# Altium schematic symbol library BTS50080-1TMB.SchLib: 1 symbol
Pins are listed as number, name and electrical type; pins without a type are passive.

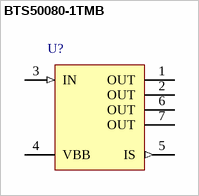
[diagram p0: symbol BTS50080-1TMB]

## BTS50080-1TMB
designator U?
Smart High-Side Power Switch PROFET, 1 Channel, 12 A Load Current, -40 to 150 degC, PG-TO220-7-12, Reel, Green; Manufacturer: Infineon; PartNumber: BTS50080-1TMB; Channels: 1; Green: TRUE; Group: Automotive Qualified; Load Current (typ): 12 A; Ptot (max): 81 W; Recommended Operating Voltage Max.: 38 V; Recommended Operating Voltage Min.: 5.5 V; RON @ 25degreesC: 8 mOhm; RON(max) @ 150degreesC: 16 mOhm; toff (max): 600 us; ton (max): 550 us
footprint INF-PG-TO220-7-12 (FM, 7-Leads, Body 10x4.4mm, Pitch 1.27mm)
pins: 1 OUT (power) "Output to the load. The pins1,2,6 and 7 must be shorted with each other especially in high current applications!", 2 OUT (power) "Output to the load. The pins1,2,6 and 7 must be shorted with each other especially in high current applications!", 3 IN (in) "Input, activates the power switch in case of short to ground", 4 VBB (power) "Positive power supply voltage, the tab is electrically connected to this pin. In high current applications the tab should be used for the Vbb connection instead of this pin", 5 IS (out) "Diagnostic feedback providing a sense current proportional to the load current; zero current on failure (see Truth Table on page 7)", 6 OUT (power) "Output to the load. The pins1,2,6 and 7 must be shorted with each other especially in high current applications!", 7 OUT (power) "Output to the load. The pins1,2,6 and 7 must be shorted with each other especially in high current applications!"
